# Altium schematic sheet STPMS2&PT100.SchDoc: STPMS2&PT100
size A3; DocumentNumber: MB1144; Revision: B-02; SheetNumber: 21; SheetTotal: 25; Project: STM32L476G-EVAL
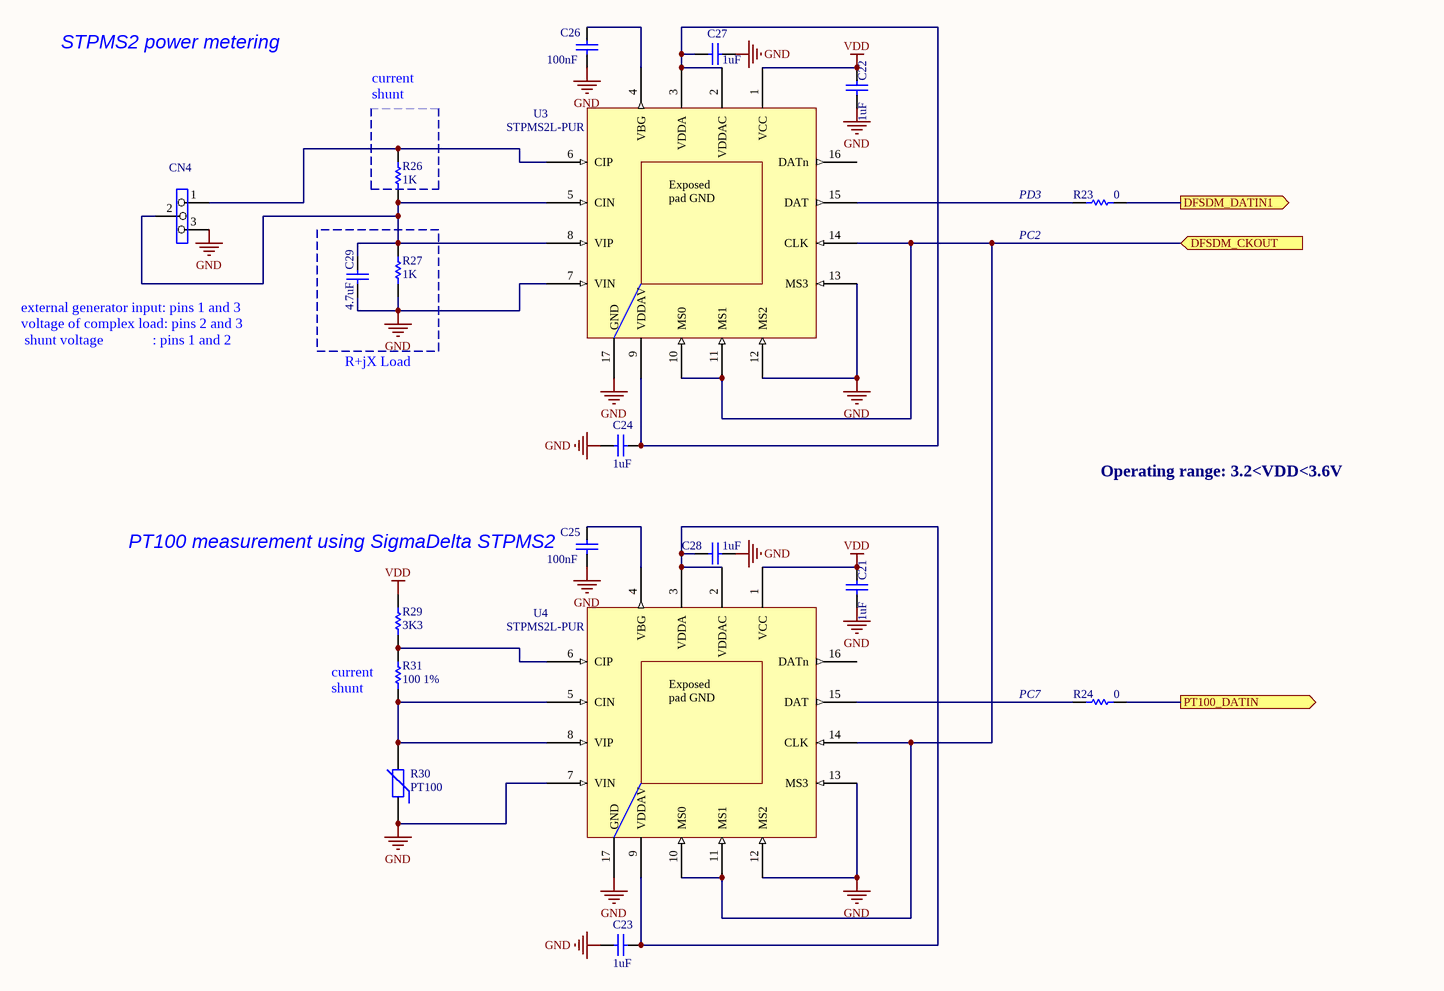
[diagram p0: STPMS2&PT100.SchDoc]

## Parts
C21  1uF  [0603C]
C22  1uF  [0603C]
C23  1uF  [0603C]
C24  1uF  [0603C]
C25  100nF  [0402C]
C26  100nF  [0402C]
C27  1uF  [0603C]
C28  1uF  [0603C]
C29  4.7uF  [0603C]
CN4  Header 3X1  [SIP3]  (value not drawn)
R23  0  [0603R]
R24  0  [0603R]
R26  1K  [0402R]
R27  1K  [0402R]
R29  3K3  [0402R]
R30  PT100  [HDR_1X2_1R27]
R31  100 1%  [0603R]
U3  STPMS2L-PUR  [QFN16_0R65_4X4]
U4  STPMS2L-PUR  [QFN16_0R65_4X4]

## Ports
DFSDM_CKOUT (in), DFSDM_DATIN1 (out), PT100_DATIN (out)

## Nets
GND: C21.2 C22.2 C23.1 C24.1 C25.1 C26.1 C27.2 C28.2 C29.2 CN4.3 R27.2 R30.1 U3.7(VIN) U3.12(MS2) U3.13(MS3) U3.17(GND) U4.7(VIN) U4.12(MS2) U4.13(MS3) U4.17(GND)
VDD: C21.1 C22.1 R29.1 U3.1(VCC) U4.1(VCC)
DFSDM_CKOUT: U3.10(MS0) U3.11(MS1) U3.14(CLK) U4.10(MS0) U4.11(MS1) U4.14(CLK) ; port DFSDM_CKOUT
DFSDM_DATIN1: R23.1 ; port DFSDM_DATIN1
PT100_DATIN: R24.1 ; port PT100_DATIN
NetC23_2: C23.2 C28.1 U4.2(VDDAC) U4.3(VDDA) U4.9(VDDAV)
NetC24_2: C24.2 C27.1 U3.2(VDDAC) U3.3(VDDA) U3.9(VDDAV)
NetC25_2: C25.2 U4.4(VBG)
NetC26_2: C26.2 U3.4(VBG)
NetC29_1: C29.1 CN4.2 R26.2 R27.1 U3.5(CIN) U3.8(VIP)
NetCN4_1: CN4.1 R26.1 U3.6(CIP)
NetR23_2: R23.2 U3.15(DAT)
NetR24_2: R24.2 U4.15(DAT)
NetR29_2: R29.2 R31.1 U4.6(CIP)
NetR30_2: R30.2 R31.2 U4.5(CIN) U4.8(VIP)

Not connected (* = marked no-connect by the designer): U3 16(DATn); U4 16(DATn)

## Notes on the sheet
- STPMS2 power metering
- current shunt
- (near R23) PD3
- PC2
- external generator input: pins 1 and 3
  voltage of complex load: pins 2 and 3
  shunt voltage              : pins 1 and 2
- R+jX Load
- PT100 measurement using SigmaDelta STPMS2
- Operating range: 3.2<VDD<3.6V
- (near R31) current shunt
- (near R24) PC7

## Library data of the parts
C21-C24 C27-C29 = CAP: Capacitor; Value: 100nF; Ordered by: Subcon; ECCN_US/EU: NA
C25 C26 = Cap: Capacitor; Value: 10nF; Ordered by: Subcon; ECCN_US/EU: NA
CN4 = Jumper3: Ordered by: Subcon; ECCN_US/EU: NA
R23 R24 = res1: Resistor; Value: 1K; Ordered by: Subcon; ECCN_US/EU: NA
R26 R27 = Res1: Resistor; Ordered by: Subcon; ECCN_US/EU: NA
R29 R31 = Res1: Resistor; Value: 1K; Ordered by: Subcon; ECCN_US/EU: NA
R30 = PT100: Varistor (Voltage-Sensitive Resistor); ECCN_US/EU: NA; Ordered by: Subcon
U3 U4 = STPMS2: STM sigmaDelta modulator; Ordered by: ST; ECCN_US/EU: EAR99/NEC; Ref St: 9177717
